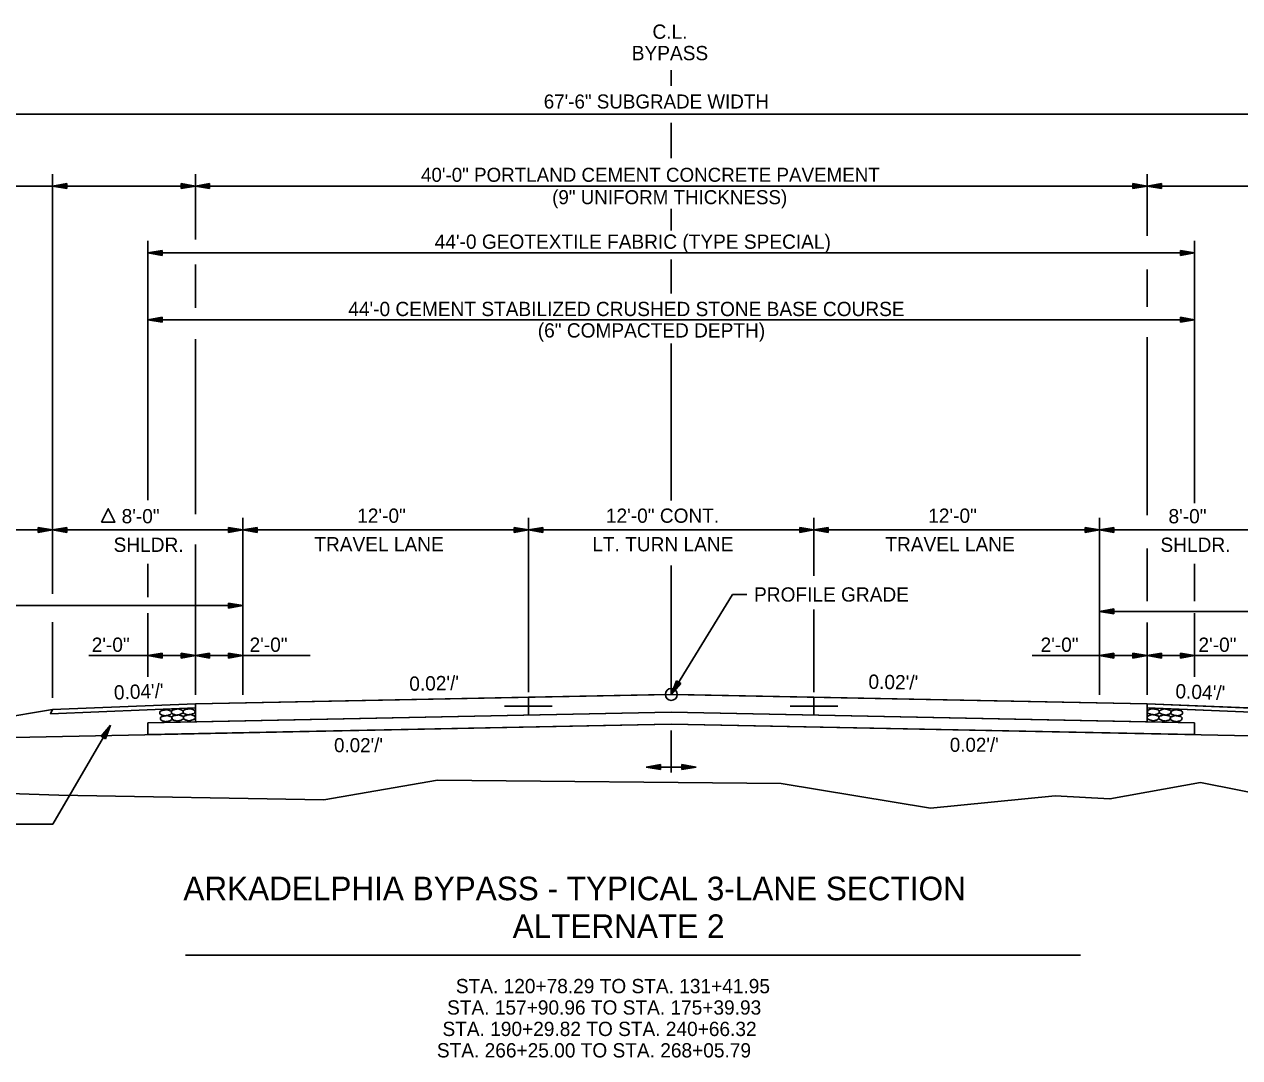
# Model space of a CAD drawing. Extents: x 1001270 to 1003428, y 1840152 to 1842912.
# Drawn here: x 1003320.9 to 1003372, y 1842664.8 to 1842708.2 of the extents above; entities that cross this region are included whole.
import ezdxf

# ---------------------------------------------------------------- set-up
doc = ezdxf.new("R2010")
doc.units = 0
for name, color, linetype in [('1', 7, 'Continuous'), ('19', 7, 'Continuous'), ('Level 1', 7, 'Continuous')]:
    doc.layers.add(name, color=color, linetype=linetype)

# ---------------------------------------------------------------- blocks, each defined once
blk = doc.blocks.new('ROCKS')
at = {"layer": '1'}
blk.add_spline([(0.013, 0.06), (0.053, 0.053), (0.107, 0.033), (0.133, 0.013), (0.133, -0.007), (0.12, -0.033), (0.107, -0.04), (0.073, -0.053), (0.033, -0.067), (0.013, -0.067), (-0.02, -0.06), (-0.06, -0.053), (-0.087, -0.047), (-0.113, -0.02), (-0.113, -0.007), (-0.107, 0.02), (-0.087, 0.033), (-0.067, 0.047), (-0.033, 0.053), (-0.02, 0.06), (0.013, 0.06)], degree=3, dxfattribs=at)

msp = doc.modelspace()

# ---------------------------------------------------------------- linework, layer by layer
at = {"layer": '19'}
for p, q in [((1003348.094, 1842705.612), (1003348.094, 1842706.264)), ((1003314.389, 1842704.422), (1003381.798, 1842704.422)), ((1003348.094, 1842702.57), (1003348.094, 1842704.053)), ((1003322.094, 1842684.256), (1003322.094, 1842701.895)), ((1003328.094, 1842699.147), (1003328.094, 1842701.895)), ((1003368.094, 1842699.304), (1003368.094, 1842701.895)), ((1003305.147, 1842701.395), (1003391.043, 1842701.395)), ((1003322.694, 1842701.5), (1003322.094, 1842701.395)), ((1003322.094, 1842701.395), (1003322.694, 1842701.29)), ((1003322.694, 1842701.445), (1003322.254, 1842701.41)), ((1003322.254, 1842701.38), (1003322.694, 1842701.34)), ((1003322.694, 1842701.29), (1003322.694, 1842701.5)), ((1003327.494, 1842701.29), (1003327.494, 1842701.5)), ((1003327.494, 1842701.5), (1003328.094, 1842701.395)), ((1003327.494, 1842701.445), (1003327.934, 1842701.41)), ((1003328.094, 1842701.395), (1003327.494, 1842701.29)), ((1003327.934, 1842701.38), (1003327.494, 1842701.34)), ((1003328.694, 1842701.5), (1003328.094, 1842701.395)), ((1003328.094, 1842701.395), (1003328.694, 1842701.29)), ((1003328.694, 1842701.445), (1003328.254, 1842701.41)), ((1003328.254, 1842701.38), (1003328.694, 1842701.34)), ((1003328.694, 1842701.29), (1003328.694, 1842701.5)), ((1003367.494, 1842701.29), (1003367.494, 1842701.5)), ((1003367.494, 1842701.5), (1003368.094, 1842701.395)), ((1003367.494, 1842701.445), (1003367.934, 1842701.41)), ((1003368.094, 1842701.395), (1003367.494, 1842701.29)), ((1003367.934, 1842701.38), (1003367.494, 1842701.34)), ((1003368.694, 1842701.5), (1003368.094, 1842701.395)), ((1003368.094, 1842701.395), (1003368.694, 1842701.29)), ((1003368.694, 1842701.445), (1003368.254, 1842701.41)), ((1003368.254, 1842701.38), (1003368.694, 1842701.34)), ((1003368.694, 1842701.29), (1003368.694, 1842701.5)), ((1003348.093, 1842699.534), (1003348.093, 1842700.442)), ((1003326.094, 1842688.203), (1003326.094, 1842699.088)), ((1003370.094, 1842688.075), (1003370.094, 1842699.088)), ((1003326.694, 1842698.693), (1003326.094, 1842698.588)), ((1003326.094, 1842698.588), (1003326.694, 1842698.483)), ((1003370.094, 1842698.588), (1003326.094, 1842698.588)), ((1003326.694, 1842698.638), (1003326.254, 1842698.603)), ((1003326.254, 1842698.573), (1003326.694, 1842698.533)), ((1003326.694, 1842698.483), (1003326.694, 1842698.693)), ((1003348.093, 1842696.881), (1003348.093, 1842698.303)), ((1003369.494, 1842698.483), (1003369.494, 1842698.693)), ((1003369.494, 1842698.693), (1003370.094, 1842698.588)), ((1003369.494, 1842698.638), (1003369.934, 1842698.603)), ((1003370.094, 1842698.588), (1003369.494, 1842698.483)), ((1003369.934, 1842698.573), (1003369.494, 1842698.533)), ((1003328.094, 1842696.274), (1003328.094, 1842698.096)), ((1003368.094, 1842696.317), (1003368.094, 1842697.885)), ((1003326.694, 1842695.886), (1003326.094, 1842695.781)), ((1003326.094, 1842695.781), (1003326.694, 1842695.676)), ((1003370.094, 1842695.781), (1003326.094, 1842695.781)), ((1003326.694, 1842695.831), (1003326.254, 1842695.796)), ((1003326.254, 1842695.766), (1003326.694, 1842695.726)), ((1003326.694, 1842695.676), (1003326.694, 1842695.886)), ((1003369.494, 1842695.676), (1003369.494, 1842695.886)), ((1003369.494, 1842695.886), (1003370.094, 1842695.781)), ((1003369.494, 1842695.831), (1003369.934, 1842695.796)), ((1003370.094, 1842695.781), (1003369.494, 1842695.676)), ((1003369.934, 1842695.766), (1003369.494, 1842695.726)), ((1003328.094, 1842687.608), (1003328.094, 1842694.957)), ((1003348.094, 1842688.185), (1003348.094, 1842694.787)), ((1003368.094, 1842687.565), (1003368.094, 1842695.042)), ((1003321.493, 1842686.841), (1003321.493, 1842687.051)), ((1003321.493, 1842687.051), (1003322.093, 1842686.946)), ((1003321.493, 1842686.996), (1003321.933, 1842686.961)), ((1003322.694, 1842687.051), (1003322.094, 1842686.946)), ((1003322.694, 1842686.996), (1003322.254, 1842686.961)), ((1003322.694, 1842686.841), (1003322.694, 1842687.051)), ((1003329.494, 1842687.051), (1003329.494, 1842686.841)), ((1003330.094, 1842686.946), (1003329.494, 1842687.051)), ((1003329.934, 1842686.961), (1003329.494, 1842686.996)), ((1003330.094, 1842680.018), (1003330.094, 1842687.462)), ((1003330.094, 1842680.096), (1003330.094, 1842687.246)), ((1003330.694, 1842687.051), (1003330.094, 1842686.946)), ((1003330.694, 1842686.996), (1003330.254, 1842686.961)), ((1003330.694, 1842686.841), (1003330.694, 1842687.051)), ((1003341.494, 1842687.051), (1003341.494, 1842686.841)), ((1003342.094, 1842686.946), (1003341.494, 1842687.051)), ((1003341.934, 1842686.961), (1003341.494, 1842686.996)), ((1003342.094, 1842680.126), (1003342.094, 1842687.462)), ((1003342.094, 1842686.946), (1003342.694, 1842687.051)), ((1003342.254, 1842686.961), (1003342.694, 1842686.996)), ((1003342.694, 1842687.051), (1003342.694, 1842686.841)), ((1003353.494, 1842687.051), (1003353.494, 1842686.841)), ((1003354.094, 1842686.946), (1003353.494, 1842687.051)), ((1003353.934, 1842686.961), (1003353.494, 1842686.996)), ((1003354.094, 1842685.012), (1003354.094, 1842687.462)), ((1003354.094, 1842686.946), (1003354.694, 1842687.051)), ((1003354.254, 1842686.961), (1003354.694, 1842686.996)), ((1003354.694, 1842687.051), (1003354.694, 1842686.841)), ((1003365.494, 1842686.841), (1003365.494, 1842687.051)), ((1003365.494, 1842687.051), (1003366.094, 1842686.946)), ((1003365.494, 1842686.996), (1003365.934, 1842686.961)), ((1003366.094, 1842680.018), (1003366.094, 1842687.462)), ((1003366.094, 1842686.946), (1003366.694, 1842687.051)), ((1003366.254, 1842686.961), (1003366.694, 1842686.996)), ((1003366.694, 1842687.051), (1003366.694, 1842686.841)), ((1003314.389, 1842686.946), (1003330.094, 1842686.946)), ((1003322.093, 1842686.946), (1003321.493, 1842686.841)), ((1003321.933, 1842686.931), (1003321.493, 1842686.891)), ((1003322.094, 1842686.946), (1003322.694, 1842686.841)), ((1003322.254, 1842686.931), (1003322.694, 1842686.891)), ((1003329.494, 1842686.841), (1003330.094, 1842686.946)), ((1003329.494, 1842686.891), (1003329.934, 1842686.931)), ((1003330.094, 1842686.946), (1003330.694, 1842686.841)), ((1003330.094, 1842686.946), (1003342.094, 1842686.946)), ((1003330.254, 1842686.931), (1003330.694, 1842686.891)), ((1003341.494, 1842686.841), (1003342.094, 1842686.946)), ((1003341.494, 1842686.891), (1003341.934, 1842686.931)), ((1003342.094, 1842686.946), (1003354.094, 1842686.946)), ((1003342.694, 1842686.841), (1003342.094, 1842686.946)), ((1003342.694, 1842686.891), (1003342.254, 1842686.931)), ((1003353.494, 1842686.841), (1003354.094, 1842686.946)), ((1003353.494, 1842686.891), (1003353.934, 1842686.931)), ((1003354.094, 1842686.946), (1003366.094, 1842686.946)), ((1003354.694, 1842686.841), (1003354.094, 1842686.946)), ((1003354.694, 1842686.891), (1003354.254, 1842686.931)), ((1003366.094, 1842686.946), (1003365.494, 1842686.841)), ((1003365.934, 1842686.931), (1003365.494, 1842686.891)), ((1003381.798, 1842686.946), (1003366.094, 1842686.946)), ((1003366.694, 1842686.841), (1003366.094, 1842686.946)), ((1003366.694, 1842686.891), (1003366.254, 1842686.931)), ((1003328.094, 1842680.018), (1003328.094, 1842686.333)), ((1003368.094, 1842683.954), (1003368.094, 1842686.163)), ((1003326.094, 1842684.124), (1003326.094, 1842685.526)), ((1003348.094, 1842680.036), (1003348.094, 1842685.459)), ((1003370.094, 1842683.954), (1003370.094, 1842685.526)), ((1003300.094, 1842683.767), (1003330.094, 1842683.767)), ((1003326.094, 1842680.776), (1003326.094, 1842683.444)), ((1003329.494, 1842683.872), (1003329.494, 1842683.662)), ((1003330.094, 1842683.767), (1003329.494, 1842683.872)), ((1003329.934, 1842683.782), (1003329.494, 1842683.817)), ((1003329.494, 1842683.662), (1003330.094, 1842683.767)), ((1003329.494, 1842683.712), (1003329.934, 1842683.752)), ((1003354.094, 1842680.126), (1003354.094, 1842683.605)), ((1003366.094, 1842683.527), (1003366.694, 1842683.632)), ((1003396.094, 1842683.527), (1003366.094, 1842683.527)), ((1003366.694, 1842683.422), (1003366.094, 1842683.527)), ((1003366.254, 1842683.542), (1003366.694, 1842683.577)), ((1003366.694, 1842683.472), (1003366.254, 1842683.512)), ((1003366.694, 1842683.632), (1003366.694, 1842683.422)), ((1003370.094, 1842680.776), (1003370.094, 1842683.444)), ((1003322.094, 1842679.886), (1003322.094, 1842683.075)), ((1003368.094, 1842680.018), (1003368.094, 1842683.062)), ((1003323.612, 1842681.665), (1003332.92, 1842681.665)), ((1003326.694, 1842681.77), (1003326.094, 1842681.665)), ((1003326.094, 1842681.665), (1003326.694, 1842681.56)), ((1003326.694, 1842681.715), (1003326.254, 1842681.68)), ((1003326.254, 1842681.65), (1003326.694, 1842681.61)), ((1003326.694, 1842681.56), (1003326.694, 1842681.77)), ((1003327.494, 1842681.56), (1003327.494, 1842681.77)), ((1003327.494, 1842681.77), (1003328.094, 1842681.665)), ((1003327.494, 1842681.715), (1003327.934, 1842681.68)), ((1003328.094, 1842681.665), (1003327.494, 1842681.56)), ((1003327.934, 1842681.65), (1003327.494, 1842681.61)), ((1003328.694, 1842681.77), (1003328.094, 1842681.665)), ((1003328.094, 1842681.665), (1003328.694, 1842681.56)), ((1003328.694, 1842681.715), (1003328.254, 1842681.68)), ((1003328.254, 1842681.65), (1003328.694, 1842681.61)), ((1003328.694, 1842681.56), (1003328.694, 1842681.77)), ((1003329.494, 1842681.77), (1003329.494, 1842681.56)), ((1003330.094, 1842681.665), (1003329.494, 1842681.77)), ((1003329.934, 1842681.68), (1003329.494, 1842681.715)), ((1003329.494, 1842681.56), (1003330.094, 1842681.665)), ((1003329.494, 1842681.61), (1003329.934, 1842681.65)), ((1003372.575, 1842681.665), (1003363.267, 1842681.665)), ((1003366.094, 1842681.665), (1003366.694, 1842681.77)), ((1003366.694, 1842681.56), (1003366.094, 1842681.665)), ((1003366.254, 1842681.68), (1003366.694, 1842681.715)), ((1003366.694, 1842681.61), (1003366.254, 1842681.65)), ((1003366.694, 1842681.77), (1003366.694, 1842681.56)), ((1003367.494, 1842681.56), (1003367.494, 1842681.77)), ((1003367.494, 1842681.77), (1003368.094, 1842681.665)), ((1003367.494, 1842681.715), (1003367.934, 1842681.68)), ((1003368.094, 1842681.665), (1003367.494, 1842681.56)), ((1003367.934, 1842681.65), (1003367.494, 1842681.61)), ((1003368.694, 1842681.77), (1003368.094, 1842681.665)), ((1003368.094, 1842681.665), (1003368.694, 1842681.56)), ((1003368.694, 1842681.715), (1003368.254, 1842681.68)), ((1003368.254, 1842681.65), (1003368.694, 1842681.61)), ((1003368.694, 1842681.56), (1003368.694, 1842681.77)), ((1003369.494, 1842681.56), (1003369.494, 1842681.77)), ((1003369.494, 1842681.77), (1003370.094, 1842681.665)), ((1003369.494, 1842681.715), (1003369.934, 1842681.68)), ((1003370.094, 1842681.665), (1003369.494, 1842681.56)), ((1003369.934, 1842681.65), (1003369.494, 1842681.61)), ((1003348.094, 1842680.036), (1003348.317, 1842680.602)), ((1003348.495, 1842680.493), (1003348.094, 1842680.036)), ((1003348.167, 1842680.176), (1003348.36, 1842680.57)), ((1003348.454, 1842680.514), (1003348.19, 1842680.165)), ((1003348.317, 1842680.602), (1003348.495, 1842680.493)), ((1003348.094, 1842680.036), (1003328.094, 1842679.636)), ((1003342.094, 1842679.165), (1003342.094, 1842679.915)), ((1003348.094, 1842680.036), (1003368.094, 1842679.636)), ((1003354.094, 1842679.166), (1003354.094, 1842679.916)), ((1003300.094, 1842675.729), (1003322.094, 1842679.396)), ((1003328.094, 1842679.469), (1003322.009, 1842679.226)), ((1003322.094, 1842679.396), (1003322.009, 1842679.226)), ((1003328.094, 1842679.636), (1003322.094, 1842679.396)), ((1003328.094, 1842679.636), (1003328.094, 1842678.886)), ((1003341.094, 1842679.54), (1003343.094, 1842679.54)), ((1003353.094, 1842679.541), (1003355.094, 1842679.541)), ((1003368.094, 1842679.636), (1003374.094, 1842679.396)), ((1003368.094, 1842678.886), (1003368.094, 1842679.636)), ((1003368.094, 1842679.469), (1003374.179, 1842679.226)), ((1003326.094, 1842678.846), (1003326.094, 1842678.346)), ((1003328.094, 1842678.886), (1003348.094, 1842679.286)), ((1003348.094, 1842679.286), (1003368.094, 1842678.886)), ((1003370.094, 1842678.346), (1003370.094, 1842678.846)), ((1003348.094, 1842678.786), (1003314.389, 1842678.112)), ((1003322.107, 1842674.579), (1003324.533, 1842678.746)), ((1003324.533, 1842678.746), (1003324.141, 1842678.28)), ((1003324.141, 1842678.28), (1003324.322, 1842678.176)), ((1003324.443, 1842678.614), (1003324.189, 1842678.256)), ((1003324.28, 1842678.201), (1003324.467, 1842678.6)), ((1003324.322, 1842678.176), (1003324.533, 1842678.746)), ((1003326.094, 1842678.346), (1003348.094, 1842678.786)), ((1003348.093, 1842678.524), (1003348.093, 1842676.755)), ((1003348.094, 1842678.786), (1003381.798, 1842678.112)), ((1003348.094, 1842678.786), (1003370.094, 1842678.346)), ((1003347.645, 1842677.085), (1003347.045, 1842676.98)), ((1003347.045, 1842676.98), (1003347.645, 1842676.875)), ((1003347.045, 1842676.98), (1003349.14, 1842676.98)), ((1003347.645, 1842677.03), (1003347.205, 1842676.995)), ((1003347.205, 1842676.965), (1003347.645, 1842676.925)), ((1003347.645, 1842676.875), (1003347.645, 1842677.085)), ((1003348.54, 1842676.875), (1003348.54, 1842677.085)), ((1003348.54, 1842677.085), (1003349.14, 1842676.98)), ((1003348.54, 1842677.03), (1003348.98, 1842676.995)), ((1003349.14, 1842676.98), (1003348.54, 1842676.875)), ((1003348.98, 1842676.965), (1003348.54, 1842676.925)), ((1003317.893, 1842674.579), (1003322.107, 1842674.579)), ((1003327.683, 1842669.082), (1003365.296, 1842669.082))]:
    msp.add_line(p, q, dxfattribs=at)
for points in [[(1003324.152, 1842687.276), (1003324.433, 1842687.839), (1003324.714, 1842687.276)], [(1003322.094, 1842679.396), (1003322.009, 1842679.226), (1003328.094, 1842679.469), (1003328.094, 1842679.636)], [(1003374.094, 1842679.396), (1003374.179, 1842679.226), (1003368.094, 1842679.469), (1003368.094, 1842679.636)]]:
    msp.add_lwpolyline(points, close=True, dxfattribs=at)
for points in [[(1003351.276, 1842684.235), (1003350.676, 1842684.234), (1003348.094, 1842680.036)], [(1003347.847, 1842680.031), (1003342.094, 1842679.916), (1003328.094, 1842679.636)], [(1003368.094, 1842679.636), (1003354.094, 1842679.916), (1003348.347, 1842680.031)], [(1003328.094, 1842678.886), (1003328.094, 1842679.636)], [(1003368.094, 1842678.886), (1003368.094, 1842679.636)], [(1003348.094, 1842679.286), (1003326.094, 1842678.846)], [(1003348.094, 1842679.286), (1003328.094, 1842678.886), (1003326.094, 1842678.846)], [(1003326.094, 1842678.346), (1003326.094, 1842678.846)], [(1003348.094, 1842679.286), (1003370.094, 1842678.846)], [(1003370.094, 1842678.846), (1003368.094, 1842678.886), (1003348.094, 1842679.286)], [(1003370.094, 1842678.346), (1003370.094, 1842678.846)], [(1003277.614, 1842677.159), (1003281.998, 1842677.23), (1003287.741, 1842677.06), (1003292.478, 1842677.542), (1003299.632, 1842677.226), (1003306.993, 1842676.318), (1003322.358, 1842675.803), (1003333.488, 1842675.604), (1003338.274, 1842676.432), (1003352.72, 1842676.291), (1003358.998, 1842675.251), (1003364.235, 1842675.775), (1003366.532, 1842675.647), (1003370.336, 1842676.334), (1003376.702, 1842675.08), (1003385.85, 1842674.465), (1003391.912, 1842673.921), (1003396.022, 1842672.287), (1003402.77, 1842671.198), (1003407.685, 1842671.825), (1003421.251, 1842671.899)]]:
    msp.add_lwpolyline(points, dxfattribs=at)
msp.add_circle((1003348.097, 1842680.034), 0.25, dxfattribs=at)
msp.add_arc((1003348.097, 1842680.034), 0.25, 180.6225, 359.3424, dxfattribs=at)

# ---------------------------------------------------------------- block references
at = {"layer": 'Level 1', "xscale": 2.0116542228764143}
for p, yscale, rotation in [((1003326.828, 1842679.259), -2.0116542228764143, 1.7446044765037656), ((1003327.313, 1842679.291), -2.0116542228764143, 1.7446044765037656), ((1003327.809, 1842679.3), -2.0116542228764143, 1.7446044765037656), ((1003368.378, 1842679.3), 2.0116542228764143, 178.25539552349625), ((1003368.874, 1842679.291), 2.0116542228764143, 178.25539552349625), ((1003369.359, 1842679.259), 2.0116542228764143, 178.25539552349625), ((1003326.853, 1842679.015), -2.0116542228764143, 1.7446044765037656), ((1003327.329, 1842679.043), -2.0116542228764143, 1.7446044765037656), ((1003327.825, 1842679.053), -2.0116542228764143, 1.7446044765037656), ((1003368.363, 1842679.053), 2.0116542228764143, 178.25539552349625), ((1003368.858, 1842679.043), 2.0116542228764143, 178.25539552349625), ((1003369.334, 1842679.015), 2.0116542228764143, 178.25539552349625)]:
    msp.add_blockref('ROCKS', p, dxfattribs=dict(at, yscale=yscale, rotation=rotation))

# ---------------------------------------------------------------- texts
at = {"layer": '19'}
for s, height, p in [('C.L.', 0.6, (1003347.306, 1842707.582)), ('BYPASS', 0.6, (1003346.436, 1842706.682)), ('67\'-6" SUBGRADE WIDTH', 0.59001, (1003342.737, 1842704.653)), ('40\'-0" PORTLAND CEMENT CONCRETE PAVEMENT', 0.59001, (1003337.578, 1842701.573)), ('(9" UNIFORM THICKNESS)', 0.59001, (1003343.09, 1842700.633)), ("44'-0 GEOTEXTILE FABRIC (TYPE SPECIAL)", 0.6, (1003338.154, 1842698.759)), ("44'-0 CEMENT STABILIZED CRUSHED STONE BASE COURSE", 0.6, (1003334.521, 1842695.931)), ('(6" COMPACTED DEPTH)', 0.6, (1003342.486, 1842695.031)), ('8\'-0"', 0.6, (1003324.995, 1842687.225)), ('12\'-0"', 0.6, (1003334.896, 1842687.246)), ('12\'-0" CONT.', 0.6, (1003345.349, 1842687.246)), ('12\'-0"', 0.6, (1003358.896, 1842687.246)), ('8\'-0"', 0.6, (1003368.995, 1842687.225)), ('SHLDR.', 0.6, (1003324.657, 1842686.025)), ('TRAVEL LANE', 0.6, (1003333.094, 1842686.046)), ('LT. TURN LANE', 0.6, (1003344.777, 1842686.046)), ('TRAVEL LANE', 0.6, (1003357.094, 1842686.046)), ('SHLDR.', 0.6, (1003368.657, 1842686.025)), ('PROFILE GRADE', 0.6, (1003351.576, 1842683.935)), ('2\'-0"', 0.6, (1003323.738, 1842681.825)), ('2\'-0"', 0.6, (1003330.372, 1842681.825)), ('2\'-0"', 0.6, (1003363.618, 1842681.825)), ('2\'-0"', 0.6, (1003370.253, 1842681.825)), ("0.02'/'", 0.59, (1003333.923, 1842677.61)), ("0.02'/'", 0.59, (1003359.803, 1842677.625))]:
    msp.add_text(s, height=height, dxfattribs=at).set_placement(p)
for s, height, rotation, p in [("0.02'/'", 0.6, 1.1458, (1003337.091, 1842680.185)), ("0.02'/'", 0.6, 358.8542, (1003356.379, 1842680.275)), ("0.04'/'", 0.6, 2.2906, (1003324.683, 1842679.815)), ("0.04'/'", 0.6, 357.7094, (1003369.276, 1842679.879)), ('ARKADELPHIA BYPASS - TYPICAL 3-LANE SECTION', 0.98999, 359.9954, (1003327.591, 1842671.39)), ('ALTERNATE 2', 0.98999, 359.9954, (1003341.431, 1842669.805)), ('STA. 120+78.29 TO STA. 131+41.95', 0.6, 359.9954, (1003339.043, 1842667.483)), ('STA. 157+90.96 TO STA. 175+39.93', 0.6, 359.9954, (1003338.674, 1842666.584)), ('STA. 190+29.82 TO STA. 240+66.32', 0.6, 359.9954, (1003338.48, 1842665.684)), ('STA. 266+25.00 TO STA. 268+05.79', 0.6, 359.9954, (1003338.246, 1842664.784))]:
    msp.add_text(s, height=height, rotation=rotation, dxfattribs=at).set_placement(p)

doc.saveas('drawing.dxf')
